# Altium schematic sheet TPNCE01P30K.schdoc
size 127 x 101 mm
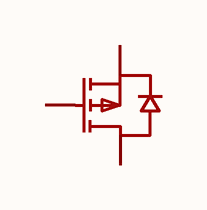
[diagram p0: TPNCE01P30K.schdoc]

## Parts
Q?  tpnce01p30k  [TO-252-2_L6.6-W6.1-P4.60-LS10.0-BR-CW]  (value not drawn)

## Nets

Not connected (* = marked no-connect by the designer): Q? 1(G) 2(D) 3(S)

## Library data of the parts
Q? = tpnce01p30k: 数量:1个P沟道;漏源电压(Vdss):100V;连续漏极电流(Id):30A;导通电阻(RDS(on)):53mΩ@10V;耗散功率(Pd):102W;阈值电压(Vgs(th)):3V;; Manufacturer: TECH PUBLIC(台舟); AddInBom: yes; ModelId: 2bfbfbb77002446c96d8a76a432e0188; ModelTransform: 246.80147,383.8575,0,90,0,0,-31.302,0.003,0; Number: 1个P沟道; Drain to Source Voltage: 100V; Current - Continuous Drain(Id): 30A; Pd - Power Dissipation: 102W; Gate Threshold Voltage (Vgs(th)): 3V; Gate Charge(Qg): 90nC@10V; Input Capacitance(Ciss): 7.8nF; Reverse Transfer Capacitance (Crss@Vds): 165pF; Type: P沟道; Output Capacitance(Coss): 222pF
